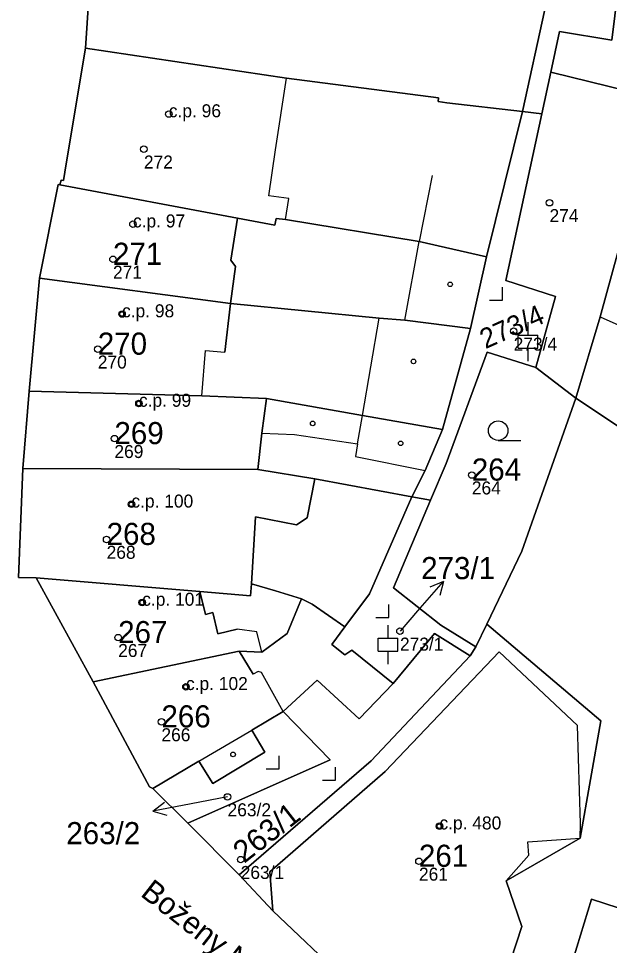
# Model space of a CAD drawing. Extents: x -878211 to -870363, y -1058464 to -1052522.
# Drawn here: x -874468.5 to -874423, y -1056220.6 to -1056149.3 of the extents above; entities that cross this region are included whole.
import ezdxf

# ---------------------------------------------------------------- set-up
doc = ezdxf.new("R2010")
doc.units = 0
for name, color, linetype in [('Definiční body', 7, 'Continuous'), ('Hranice parcel', 7, 'Continuous'), ('Parcelní čísla', 7, 'Continuous'), ('Polygon budovy', 7, 'Continuous'), ('Polygon parcely', 7, 'Continuous'), ('Pop  PČ popisy', 7, 'Continuous'), ('Vnitřní kresba', 7, 'Continuous'), ('Značky budov', 7, 'Continuous'), ('Značky kultur', 7, 'Continuous')]:
    doc.layers.add(name, color=color, linetype=linetype)

msp = doc.modelspace()

# ---------------------------------------------------------------- linework, layer by layer
at = {"layer": 'Definiční body'}
for centre in [(-874456.9, -1056156.67994), (-874458.82, -1056159.37994), (-874427.6, -1056163.49994), (-874459.66, -1056165.14994), (-874461.2, -1056167.84994), (-874460.5, -1056172.05994), (-874430.36, -1056173.37994), (-874462.37, -1056174.75994), (-874459.2, -1056178.93994), (-874461.09, -1056181.63994), (-874433.58, -1056184.43994), (-874459.78, -1056186.68994), (-874461.69, -1056189.38994), (-874458.95, -1056194.23994), (-874439.11, -1056196.44994), (-874460.8, -1056196.93994), (-874455.58, -1056200.71994), (-874457.47, -1056203.41994), (-874452.38, -1056209.18994), (-874436.07, -1056211.43994), (-874451.37, -1056214.00994), (-874437.65, -1056214.13994)]:
    msp.add_circle(centre, 0.25, dxfattribs=at)
at = {"layer": 'Hranice parcel'}
for p, q in [((-874432.46, -1056167.65), (-874429.69, -1056156.49)), ((-874430.95, -1056169.48), (-874428.2, -1056156.66)), ((-874432.46, -1056167.65), (-874437.64, -1056166.47)), ((-874433.69, -1056173.18), (-874432.46, -1056167.65)), ((-874466.85, -1056169.3), (-874467.64, -1056177.98)), ((-874433.69, -1056173.18), (-874438.73, -1056172.52)), ((-874435.84, -1056180.94), (-874433.69, -1056173.18)), ((-874425.58, -1056178.53), (-874428.66, -1056176.17)), ((-874468.14, -1056183.93), (-874467.64, -1056177.98)), ((-874418.77, -1056183.05), (-874425.58, -1056178.53)), ((-874435.56, -1056183.54), (-874436.76, -1056186.38)), ((-874436.76, -1056186.38), (-874439.61, -1056193.1)), ((-874436.76, -1056186.38), (-874438.19, -1056186.12)), ((-874462.72, -1056200.33), (-874467.1, -1056192.35)), ((-874432.43, -1056195.91), (-874433.27, -1056197.66)), ((-874433.27, -1056197.66), (-874433.7, -1056198.35)), ((-874458.14, -1056208.53), (-874455.45, -1056211.22)), ((-874455.45, -1056211.22), (-874451.49, -1056215.18))]:
    msp.add_line(p, q, dxfattribs=at)
for points in [[(-874425.58, -1056178.53), (-874423.7, -1056172.28), (-874422.31, -1056167.22), (-874420.09, -1056155.27)], [(-874465.28, -1056162.12), (-874465.42, -1056162.09), (-874466.85, -1056169.3)], [(-874437.64, -1056166.47), (-874447.93, -1056164.78), (-874448.64, -1056164.72), (-874448.75, -1056165.22), (-874451.61, -1056164.69), (-874465.28, -1056162.12)], [(-874438.73, -1056172.52), (-874440.72, -1056172.38), (-874452.15, -1056171.26), (-874466.85, -1056169.3)], [(-874428.66, -1056176.17), (-874427.13, -1056170.7), (-874430.95, -1056169.48)], [(-874428.66, -1056176.17), (-874432.41, -1056174.98), (-874435.56, -1056183.54)], [(-874467.64, -1056177.98), (-874454.37, -1056178.34), (-874449.39, -1056178.56), (-874442, -1056179.86), (-874435.84, -1056180.94)], [(-874432.43, -1056195.91), (-874429.74, -1056190.29), (-874425.58, -1056178.53)], [(-874435.84, -1056180.94), (-874437.18, -1056184.09), (-874438.19, -1056186.12)], [(-874467.1, -1056192.35), (-874468.47, -1056192.32), (-874468.14, -1056183.93)], [(-874438.19, -1056186.12), (-874445.67, -1056184.74), (-874450.05, -1056184.02), (-874468.14, -1056183.93)], [(-874438.19, -1056186.12), (-874441.45, -1056193.57), (-874443.36, -1056196.1)], [(-874446.68, -1056193.96), (-874448.7, -1056193.33), (-874450.53, -1056192.81), (-874450.62, -1056193.72), (-874454.51, -1056193.4), (-874467.1, -1056192.35)], [(-874439.61, -1056193.1), (-874435.97, -1056195.97), (-874433.27, -1056197.66)], [(-874446.68, -1056193.96), (-874447.79, -1056196.62), (-874449.74, -1056198.07), (-874451.49, -1056197.99), (-874462.72, -1056200.33)], [(-874443.36, -1056196.1), (-874445.86, -1056194.37), (-874446.68, -1056193.96)], [(-874439.63, -1056200.46), (-874442.81, -1056197.9), (-874443.35, -1056198.27), (-874444.35, -1056197.47), (-874443.36, -1056196.1)], [(-874425.24, -1056212.37), (-874423.66, -1056203.35), (-874432.43, -1056195.91)], [(-874433.7, -1056198.35), (-874436.46, -1056196.62), (-874439.63, -1056200.46)], [(-874433.7, -1056198.35), (-874441.33, -1056206.41), (-874451.49, -1056215.18)], [(-874462.72, -1056200.33), (-874458.38, -1056208.41), (-874458.14, -1056208.53)], [(-874439.63, -1056200.46), (-874442.24, -1056203.18), (-874445.48, -1056200.22), (-874448.11, -1056202.63)], [(-874448.11, -1056202.63), (-874450.5, -1056204.05), (-874449.52, -1056205.76), (-874453.51, -1056208.15), (-874454.58, -1056206.45), (-874458.14, -1056208.53)], [(-874448.11, -1056202.63), (-874444.49, -1056206.35), (-874455.45, -1056211.22)], [(-874435.24, -1056228.11), (-874432.29, -1056227), (-874429.74, -1056219.15), (-874430.94, -1056215.65), (-874425.24, -1056212.37)], [(-874451.49, -1056215.18), (-874448.89, -1056217.95), (-874443.32, -1056223.23), (-874435.24, -1056228.11)], [(-874428.88, -1056231.82), (-874424.38, -1056217.04), (-874415.05, -1056220.07), (-874418.74, -1056237.49)]]:
    msp.add_lwpolyline(points, dxfattribs=at)
at = {"layer": 'Polygon budovy'}
for points in [[(-874462.35, -1056136.87), (-874463.32, -1056151.62), (-874447.84, -1056153.92), (-874436.14, -1056155.43), (-874436.17, -1056155.71), (-874435.5, -1056155.81), (-874429.69, -1056156.49), (-874427.97, -1056148.64), (-874426.71, -1056140.02), (-874434.9, -1056138.61)], [(-874463.32, -1056151.62), (-874464.8, -1056160.52), (-874465.01, -1056161.8), (-874465.19, -1056161.77), (-874465.28, -1056162.12), (-874451.61, -1056164.69), (-874448.75, -1056165.22), (-874448.64, -1056164.72), (-874447.93, -1056164.78), (-874447.66, -1056163.18), (-874449.2, -1056162.96), (-874448.69, -1056159.43), (-874447.84, -1056153.92)], [(-874451.61, -1056164.69), (-874465.28, -1056162.12), (-874465.42, -1056162.09), (-874466.85, -1056169.3), (-874452.15, -1056171.26), (-874451.77, -1056168.41), (-874452.14, -1056167.91)], [(-874466.85, -1056169.3), (-874467.64, -1056177.98), (-874454.37, -1056178.34), (-874454.08, -1056174.87), (-874452.58, -1056174.99), (-874452.15, -1056171.26)], [(-874449.39, -1056178.56), (-874454.37, -1056178.34), (-874467.64, -1056177.98), (-874468.14, -1056183.93), (-874450.05, -1056184.02), (-874449.73, -1056181.21)], [(-874446.25, -1056187.73), (-874445.67, -1056184.74), (-874450.05, -1056184.02), (-874468.14, -1056183.93), (-874468.47, -1056192.32), (-874467.1, -1056192.35), (-874454.51, -1056193.4), (-874450.62, -1056193.72), (-874450.53, -1056192.81), (-874450.23, -1056187.65), (-874447.07, -1056188.26)], [(-874449.74, -1056198.07), (-874450.14, -1056196.5), (-874451.64, -1056196.28), (-874453.12, -1056196.64), (-874453.51, -1056195.02), (-874454.08, -1056195.16), (-874454.51, -1056193.4), (-874467.1, -1056192.35), (-874462.72, -1056200.33), (-874451.49, -1056197.99)], [(-874462.72, -1056200.33), (-874458.38, -1056208.41), (-874458.14, -1056208.53), (-874454.58, -1056206.45), (-874450.5, -1056204.05), (-874448.11, -1056202.63), (-874449.78, -1056199.61), (-874450.03, -1056199.54), (-874450.41, -1056199.75), (-874451.49, -1056197.99)], [(-874432.29, -1056227), (-874429.74, -1056219.15), (-874430.94, -1056215.65), (-874429.19, -1056213.68), (-874429.26, -1056212.64), (-874425.24, -1056212.37), (-874425.22, -1056211.24), (-874425.45, -1056203.7), (-874431.48, -1056198.02), (-874440.26, -1056207.23), (-874449.12, -1056214.95), (-874448.89, -1056217.95), (-874443.32, -1056223.23), (-874435.24, -1056228.11)], [(-874424.38, -1056217.04), (-874428.88, -1056231.82), (-874426.7, -1056234.92), (-874423.16, -1056237.73), (-874423.27, -1056237.96), (-874422.49, -1056238.33), (-874422.26, -1056238.13), (-874418.74, -1056237.49), (-874415.05, -1056220.07)]]:
    msp.add_lwpolyline(points, close=True, dxfattribs=at)
at = {"layer": 'Polygon parcely'}
for points in [[(-874443.32, -1056223.23), (-874448.89, -1056217.95), (-874451.49, -1056215.18), (-874455.45, -1056211.22), (-874458.14, -1056208.53), (-874458.38, -1056208.41), (-874462.72, -1056200.33), (-874467.1, -1056192.35), (-874468.47, -1056192.32), (-874468.14, -1056183.93), (-874467.64, -1056177.98), (-874466.85, -1056169.3), (-874465.42, -1056162.09), (-874465.28, -1056162.12), (-874465.19, -1056161.77), (-874465.01, -1056161.8), (-874464.8, -1056160.52), (-874463.32, -1056151.62), (-874462.35, -1056136.87)], [(-874403.45, -1056222.45), (-874401.81, -1056219.64), (-874401.01, -1056218.16), (-874401.77, -1056215.42), (-874404.44, -1056205.79), (-874405.36, -1056202.47), (-874405.88, -1056200.6), (-874411.33, -1056201.7), (-874421.89, -1056189.85), (-874418.77, -1056183.05), (-874425.58, -1056178.53), (-874429.74, -1056190.29), (-874432.43, -1056195.91), (-874423.66, -1056203.35), (-874425.24, -1056212.37), (-874430.94, -1056215.65), (-874429.74, -1056219.15), (-874432.29, -1056227)], [(-874428.88, -1056231.82), (-874424.38, -1056217.04), (-874415.05, -1056220.07), (-874418.74, -1056237.49)]]:
    msp.add_lwpolyline(points, dxfattribs=at)
for points in [[(-874434.9, -1056138.61), (-874462.35, -1056136.87), (-874463.32, -1056151.62), (-874447.84, -1056153.92), (-874436.14, -1056155.43), (-874436.17, -1056155.71), (-874435.5, -1056155.81), (-874429.69, -1056156.49), (-874427.97, -1056148.64), (-874426.71, -1056140.02)], [(-874422.8, -1056151.01), (-874422.08, -1056145.16), (-874424.64, -1056144.67), (-874425.69, -1056143.18), (-874425.32, -1056140.26), (-874426.71, -1056140.02), (-874427.97, -1056148.64), (-874429.69, -1056156.49), (-874428.2, -1056156.66), (-874427.51, -1056153.45), (-874426.83, -1056150.34)], [(-874399.99, -1056143.24), (-874415.13, -1056140.39), (-874415.86, -1056144.95), (-874422.08, -1056145.16), (-874422.8, -1056151.01), (-874426.83, -1056150.34), (-874427.51, -1056153.45), (-874420.09, -1056155.27), (-874419.79, -1056154.32), (-874417.07, -1056155.54), (-874410.31, -1056158.12), (-874401.94, -1056159.9), (-874401.89, -1056159.5), (-874400.52, -1056148.33)], [(-874436.17, -1056155.71), (-874436.14, -1056155.43), (-874447.84, -1056153.92), (-874463.32, -1056151.62), (-874464.8, -1056160.52), (-874465.01, -1056161.8), (-874465.19, -1056161.77), (-874465.28, -1056162.12), (-874451.61, -1056164.69), (-874448.75, -1056165.22), (-874448.64, -1056164.72), (-874447.93, -1056164.78), (-874437.64, -1056166.47), (-874432.46, -1056167.65), (-874429.69, -1056156.49), (-874435.5, -1056155.81)], [(-874423.7, -1056172.28), (-874422.31, -1056167.22), (-874420.09, -1056155.27), (-874427.51, -1056153.45), (-874428.2, -1056156.66), (-874430.95, -1056169.48), (-874427.13, -1056170.7), (-874428.66, -1056176.17), (-874425.58, -1056178.53)], [(-874401.94, -1056159.9), (-874410.31, -1056158.12), (-874417.07, -1056155.54), (-874419.79, -1056154.32), (-874420.09, -1056155.27), (-874422.31, -1056167.22), (-874423.7, -1056172.28), (-874425.58, -1056178.53), (-874418.77, -1056183.05), (-874416.51, -1056177.2), (-874402.49, -1056181.79), (-874400.97, -1056174.76), (-874400.19, -1056171), (-874399.02, -1056165.44), (-874398.01, -1056160.14), (-874401.89, -1056159.5)], [(-874428.2, -1056156.66), (-874429.69, -1056156.49), (-874432.46, -1056167.65), (-874433.69, -1056173.18), (-874435.84, -1056180.94), (-874437.18, -1056184.09), (-874438.19, -1056186.12), (-874436.76, -1056186.38), (-874435.56, -1056183.54), (-874432.41, -1056174.98), (-874428.66, -1056176.17), (-874427.13, -1056170.7), (-874430.95, -1056169.48)], [(-874447.93, -1056164.78), (-874448.64, -1056164.72), (-874448.75, -1056165.22), (-874451.61, -1056164.69), (-874465.28, -1056162.12), (-874465.42, -1056162.09), (-874466.85, -1056169.3), (-874452.15, -1056171.26), (-874440.72, -1056172.38), (-874438.73, -1056172.52), (-874433.69, -1056173.18), (-874432.46, -1056167.65), (-874437.64, -1056166.47)], [(-874454.37, -1056178.34), (-874449.39, -1056178.56), (-874442, -1056179.86), (-874435.84, -1056180.94), (-874433.69, -1056173.18), (-874438.73, -1056172.52), (-874440.72, -1056172.38), (-874452.15, -1056171.26), (-874466.85, -1056169.3), (-874467.64, -1056177.98)], [(-874435.56, -1056183.54), (-874436.76, -1056186.38), (-874439.61, -1056193.1), (-874435.97, -1056195.97), (-874433.27, -1056197.66), (-874432.43, -1056195.91), (-874429.74, -1056190.29), (-874425.58, -1056178.53), (-874428.66, -1056176.17), (-874432.41, -1056174.98)], [(-874435.84, -1056180.94), (-874442, -1056179.86), (-874449.39, -1056178.56), (-874454.37, -1056178.34), (-874467.64, -1056177.98), (-874468.14, -1056183.93), (-874450.05, -1056184.02), (-874445.67, -1056184.74), (-874438.19, -1056186.12), (-874437.18, -1056184.09)], [(-874438.19, -1056186.12), (-874445.67, -1056184.74), (-874450.05, -1056184.02), (-874468.14, -1056183.93), (-874468.47, -1056192.32), (-874467.1, -1056192.35), (-874454.51, -1056193.4), (-874450.62, -1056193.72), (-874450.53, -1056192.81), (-874448.7, -1056193.33), (-874446.68, -1056193.96), (-874445.86, -1056194.37), (-874443.36, -1056196.1), (-874441.45, -1056193.57)], [(-874441.45, -1056193.57), (-874443.36, -1056196.1), (-874444.35, -1056197.47), (-874443.35, -1056198.27), (-874442.81, -1056197.9), (-874439.63, -1056200.46), (-874436.46, -1056196.62), (-874433.7, -1056198.35), (-874433.27, -1056197.66), (-874435.97, -1056195.97), (-874439.61, -1056193.1), (-874436.76, -1056186.38), (-874438.19, -1056186.12)], [(-874454.51, -1056193.4), (-874467.1, -1056192.35), (-874462.72, -1056200.33), (-874451.49, -1056197.99), (-874449.74, -1056198.07), (-874447.79, -1056196.62), (-874446.68, -1056193.96), (-874448.7, -1056193.33), (-874450.53, -1056192.81), (-874450.62, -1056193.72)], [(-874451.49, -1056197.99), (-874462.72, -1056200.33), (-874458.38, -1056208.41), (-874458.14, -1056208.53), (-874454.58, -1056206.45), (-874453.51, -1056208.15), (-874449.52, -1056205.76), (-874450.5, -1056204.05), (-874448.11, -1056202.63), (-874445.48, -1056200.22), (-874442.24, -1056203.18), (-874439.63, -1056200.46), (-874442.81, -1056197.9), (-874443.35, -1056198.27), (-874444.35, -1056197.47), (-874443.36, -1056196.1), (-874445.86, -1056194.37), (-874446.68, -1056193.96), (-874447.79, -1056196.62), (-874449.74, -1056198.07)], [(-874429.74, -1056219.15), (-874430.94, -1056215.65), (-874425.24, -1056212.37), (-874423.66, -1056203.35), (-874432.43, -1056195.91), (-874433.27, -1056197.66), (-874433.7, -1056198.35), (-874441.33, -1056206.41), (-874451.49, -1056215.18), (-874448.89, -1056217.95), (-874443.32, -1056223.23), (-874435.24, -1056228.11), (-874432.29, -1056227)], [(-874448.11, -1056202.63), (-874444.49, -1056206.35), (-874455.45, -1056211.22), (-874451.49, -1056215.18), (-874441.33, -1056206.41), (-874433.7, -1056198.35), (-874436.46, -1056196.62), (-874439.63, -1056200.46), (-874442.24, -1056203.18), (-874445.48, -1056200.22)], [(-874454.58, -1056206.45), (-874458.14, -1056208.53), (-874455.45, -1056211.22), (-874444.49, -1056206.35), (-874448.11, -1056202.63), (-874450.5, -1056204.05), (-874449.52, -1056205.76), (-874453.51, -1056208.15)], [(-874418.74, -1056237.49), (-874415.05, -1056220.07), (-874424.38, -1056217.04), (-874428.88, -1056231.82), (-874426.7, -1056234.92), (-874423.16, -1056237.73), (-874423.27, -1056237.96), (-874422.49, -1056238.33), (-874422.26, -1056238.13)]]:
    msp.add_lwpolyline(points, close=True, dxfattribs=at)
at = {"layer": 'Pop  PČ popisy'}
for p, q in [((-874437.74, -1056194.89), (-874435.771, -1056192.625)), ((-874435.771, -1056192.625), (-874436.806, -1056193.052)), ((-874435.771, -1056192.625), (-874436.05, -1056193.709)), ((-874439.07, -1056196.45), (-874437.74, -1056194.89)), ((-874452.38, -1056209.19), (-874455.18, -1056209.71)), ((-874458.126, -1056210.283), (-874457.238, -1056209.6)), ((-874455.18, -1056209.71), (-874458.126, -1056210.283)), ((-874458.126, -1056210.283), (-874457.047, -1056210.583))]:
    msp.add_line(p, q, dxfattribs=at)
at = {"layer": 'Vnitřní kresba'}
for p, q in [((-874436.62, -1056161.41), (-874437.64, -1056166.47)), ((-874451.61, -1056164.69), (-874452.14, -1056167.91)), ((-874438.73, -1056172.52), (-874437.64, -1056166.47)), ((-874452.14, -1056167.91), (-874451.77, -1056168.41)), ((-874451.77, -1056168.41), (-874452.15, -1056171.26)), ((-874452.15, -1056171.26), (-874452.58, -1056174.99)), ((-874423.7, -1056172.28), (-874419.08, -1056174.34)), ((-874442, -1056179.86), (-874440.72, -1056172.38)), ((-874454.37, -1056178.34), (-874454.08, -1056174.87)), ((-874454.08, -1056174.87), (-874452.58, -1056174.99)), ((-874449.39, -1056178.56), (-874449.73, -1056181.21)), ((-874442.37, -1056182.03), (-874442, -1056179.86)), ((-874449.73, -1056181.21), (-874450.05, -1056184.02)), ((-874449.73, -1056181.21), (-874447.23, -1056181.33)), ((-874447.23, -1056181.33), (-874442.37, -1056182.03)), ((-874442.37, -1056182.03), (-874442.54, -1056183.02)), ((-874442.54, -1056183.02), (-874437.18, -1056184.09)), ((-874445.67, -1056184.74), (-874446.25, -1056187.73)), ((-874450.23, -1056187.65), (-874450.53, -1056192.81)), ((-874447.07, -1056188.26), (-874450.23, -1056187.65)), ((-874446.25, -1056187.73), (-874447.07, -1056188.26)), ((-874454.51, -1056193.4), (-874454.08, -1056195.16)), ((-874454.08, -1056195.16), (-874453.51, -1056195.02)), ((-874453.51, -1056195.02), (-874453.12, -1056196.64)), ((-874453.12, -1056196.64), (-874451.64, -1056196.28)), ((-874450.14, -1056196.5), (-874451.64, -1056196.28)), ((-874449.74, -1056198.07), (-874450.14, -1056196.5)), ((-874451.49, -1056197.99), (-874450.41, -1056199.75)), ((-874440.26, -1056207.23), (-874431.48, -1056198.02)), ((-874431.48, -1056198.02), (-874425.45, -1056203.7)), ((-874450.03, -1056199.54), (-874450.41, -1056199.75)), ((-874449.78, -1056199.61), (-874450.03, -1056199.54)), ((-874448.11, -1056202.63), (-874449.78, -1056199.61)), ((-874425.22, -1056211.24), (-874425.45, -1056203.7)), ((-874454.58, -1056206.45), (-874450.5, -1056204.05)), ((-874449.12, -1056214.95), (-874440.26, -1056207.23)), ((-874425.24, -1056212.37), (-874425.22, -1056211.24)), ((-874429.26, -1056212.64), (-874425.24, -1056212.37)), ((-874429.19, -1056213.68), (-874429.26, -1056212.64)), ((-874430.94, -1056215.65), (-874429.19, -1056213.68)), ((-874448.89, -1056217.95), (-874449.12, -1056214.95))]:
    msp.add_line(p, q, dxfattribs=at)
at = {"layer": 'Značky budov'}
for centre in [(-874435.2468, -1056169.76916), (-874460.5068, -1056172.05916), (-874438.0668, -1056175.69916), (-874459.2068, -1056178.93916), (-874445.8268, -1056180.46916), (-874439.0568, -1056181.99916), (-874459.7868, -1056186.68916), (-874458.9568, -1056194.23916), (-874455.5868, -1056200.71916), (-874451.9568, -1056205.91916), (-874436.0768, -1056211.43916)]:
    msp.add_circle(centre, 0.175, dxfattribs=at)
at = {"layer": 'Značky kultur'}
for p, q in [((-874431.21, -1056170.98), (-874431.21, -1056169.98)), ((-874432.211, -1056170.98), (-874431.21, -1056170.98)), ((-874429.25, -1056173.681), (-874429.25, -1056172.68)), ((-874430.001, -1056173.681), (-874428.499, -1056173.681)), ((-874430.001, -1056174.682), (-874430.001, -1056173.681)), ((-874428.499, -1056174.682), (-874428.499, -1056173.681)), ((-874430.001, -1056174.682), (-874428.499, -1056174.682)), ((-874429.25, -1056175.68), (-874429.25, -1056174.682)), ((-874431.553, -1056181.77), (-874429.803, -1056181.77)), ((-874439.97, -1056195.39), (-874439.97, -1056194.39)), ((-874440.971, -1056195.39), (-874439.97, -1056195.39)), ((-874440.03, -1056196.971), (-874440.03, -1056195.97)), ((-874440.781, -1056196.971), (-874439.279, -1056196.971)), ((-874440.781, -1056197.972), (-874440.781, -1056196.971)), ((-874439.279, -1056197.972), (-874439.279, -1056196.971)), ((-874440.781, -1056197.972), (-874439.279, -1056197.972)), ((-874440.03, -1056198.97), (-874440.03, -1056197.972)), ((-874448.42, -1056207.03), (-874448.42, -1056206.03)), ((-874449.421, -1056207.03), (-874448.42, -1056207.03)), ((-874444.07, -1056207.91), (-874444.07, -1056206.91)), ((-874445.071, -1056207.91), (-874444.07, -1056207.91))]:
    msp.add_line(p, q, dxfattribs=at)
msp.add_circle((-874431.55286, -1056181.01981), 0.75, dxfattribs=at)

# ---------------------------------------------------------------- texts
at = {"layer": 'Definiční body'}
for s, p in [('c.p. 96', (-874456.9, -1056156.929)), ('272', (-874458.82, -1056160.869)), ('c.p. 97', (-874459.66, -1056165.399)), ('274', (-874427.6, -1056164.989)), ('271', (-874461.2, -1056169.339)), ('c.p. 98', (-874460.5, -1056172.31)), ('273/4', (-874430.36, -1056174.869)), ('270', (-874462.37, -1056176.249)), ('c.p. 99', (-874459.2, -1056179.19)), ('269', (-874461.09, -1056183.129)), ('264', (-874433.58, -1056185.929)), ('c.p. 100', (-874459.78, -1056186.94)), ('268', (-874461.69, -1056190.879)), ('c.p. 101', (-874458.95, -1056194.49)), ('273/1', (-874439.11, -1056197.939)), ('267', (-874460.8, -1056198.429)), ('c.p. 102', (-874455.58, -1056200.97)), ('266', (-874457.47, -1056204.909)), ('263/2', (-874452.38, -1056210.679)), ('c.p. 480', (-874436.07, -1056211.69)), ('263/1', (-874451.37, -1056215.499)), ('261', (-874437.65, -1056215.629))]:
    msp.add_text(s, height=0.999996, dxfattribs=at).set_placement(p)
at = {"layer": 'Parcelní čísla'}
for s, p in [('271', (-874461.2, -1056168.275)), ('270', (-874462.37, -1056175.185)), ('269', (-874461.09, -1056182.064)), ('264', (-874433.58, -1056184.865)), ('268', (-874461.69, -1056189.814)), ('273/1', (-874437.48, -1056192.445)), ('267', (-874460.8, -1056197.365)), ('266', (-874457.47, -1056203.844)), ('263/2', (-874464.792, -1056212.825)), ('261', (-874437.65, -1056214.564))]:
    msp.add_text(s, height=1.699998, dxfattribs=at).set_placement(p)
for s, height, rotation, p in [('273/4', 1.53, 24, (-874432.536, -1056174.767)), ('263/1', 1.699998, 38, (-874451.108, -1056214.344))]:
    msp.add_text(s, height=height, rotation=rotation, dxfattribs=at).set_placement(p)
at = {"layer": 'Pop  PČ popisy'}
msp.add_text('Boženy Nemcové', height=1.699998, rotation=321.9999972, dxfattribs=at).set_placement((-874459.161, -1056216.754))

doc.saveas('drawing.dxf')
